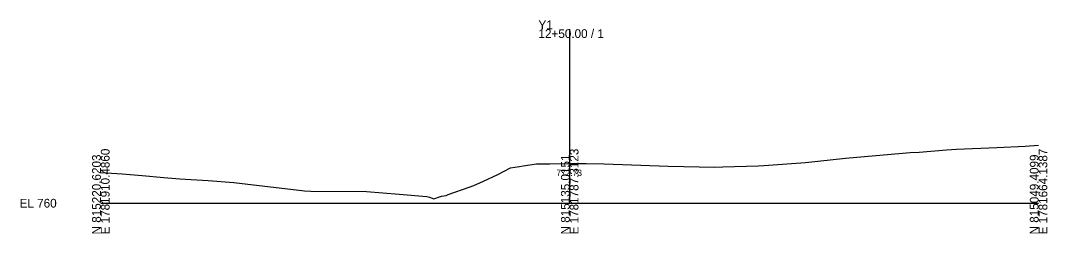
# Model space of a CAD drawing. Extents: x -26 to 3603, y -10 to 9847.
# Drawn here: x -25.7 to 302.8, y 2490.3 to 2558.5 of the extents above; entities that cross this region are included whole.
import ezdxf

# ---------------------------------------------------------------- set-up
doc = ezdxf.new("R2010")
doc.units = 0
for name, color, linetype in [('Exist Cross Section Cell', 7, 'Continuous'), ('Exist XS Center Line Elevation Label', 7, 'Continuous'), ('Exist XS Ground Line', 7, 'Continuous')]:
    doc.layers.add(name, color=color, linetype=linetype)

msp = doc.modelspace()

# ---------------------------------------------------------------- linework, layer by layer
at = {"layer": 'Exist Cross Section Cell'}
for p, q in [((150, 2500), (150, 2555.73)), ((0, 2500), (150, 2500)), ((150, 2500), (300, 2500))]:
    msp.add_line(p, q, dxfattribs=at)
at = {"layer": 'Exist XS Ground Line'}
for p, q in [((261.75, 2516.38), (270.56, 2517.06)), ((270.56, 2517.06), (273.7, 2517.35)), ((273.7, 2517.35), (286.6, 2517.87)), ((286.6, 2517.87), (295.75, 2518.32)), ((295.75, 2518.32), (300, 2518.58)), ((225.42, 2513.06), (238.2, 2514.43)), ((238.2, 2514.43), (258.92, 2516.26)), ((258.92, 2516.26), (261.75, 2516.38)), ((127.02, 2509.19), (131.05, 2511.33)), ((131.05, 2511.33), (132.42, 2511.56)), ((132.42, 2511.56), (133.89, 2511.78)), ((133.89, 2511.78), (135.09, 2511.95)), ((135.09, 2511.95), (139.33, 2512.57)), ((139.33, 2512.57), (143.61, 2512.65)), ((143.61, 2512.65), (150.07, 2512.73)), ((150.07, 2512.73), (155.22, 2512.7)), ((155.22, 2512.7), (161.06, 2512.66)), ((161.06, 2512.66), (181.52, 2511.85)), ((181.52, 2511.85), (196.42, 2511.54)), ((196.42, 2511.54), (198.96, 2511.68)), ((198.96, 2511.68), (210.31, 2512)), ((210.31, 2512), (212.05, 2512.08)), ((212.05, 2512.08), (225.42, 2513.06)), ((0, 2509.87), (6.77, 2509.39)), ((6.77, 2509.39), (13.24, 2508.83)), ((13.24, 2508.83), (20.12, 2508.27)), ((20.12, 2508.27), (25.27, 2507.79)), ((25.27, 2507.79), (34.37, 2507.23)), ((34.37, 2507.23), (42.5, 2506.66)), ((119.31, 2505.72), (122.4, 2507.03)), ((122.4, 2507.03), (127.02, 2509.19)), ((42.5, 2506.66), (65.2, 2504.01)), ((65.2, 2504.01), (67.19, 2503.82)), ((67.19, 2503.82), (85.02, 2503.73)), ((85.02, 2503.73), (95.48, 2502.93)), ((111.09, 2502.8), (117.84, 2505.13)), ((117.84, 2505.13), (119.31, 2505.72)), ((95.48, 2502.93), (104.24, 2502.14)), ((104.24, 2502.14), (105.1, 2501.89)), ((105.1, 2501.89), (106.56, 2501.41)), ((106.56, 2501.41), (108.35, 2502)), ((108.35, 2502), (109, 2502.21)), ((109, 2502.21), (110.5, 2502.49)), ((110.5, 2502.49), (111.09, 2502.8))]:
    msp.add_line(p, q, dxfattribs=at)

# ---------------------------------------------------------------- texts
at = {"layer": 'Exist Cross Section Cell'}
for s, p in [('Y1', (140, 2555.73)), ('12+50.00 / 1', (140, 2552.93)), ('EL 760', (-26, 2498.6))]:
    msp.add_text(s, height=2.8, dxfattribs=at).set_placement(p)
for s, p in [('E 1781910.4860', (2.8, 2490)), ('E 1781787.3123', (152.8, 2490)), ('E 1781664.1387', (302.8, 2490)), ('N 815220.6203', (0, 2490)), ('N 815135.0151', (150, 2490)), ('N 815049.4099', (300, 2490))]:
    msp.add_text(s, height=2.8, rotation=90, dxfattribs=at).set_placement(p)
at = {"layer": 'Exist XS Center Line Elevation Label'}
msp.add_text('772.73', height=2, dxfattribs=at).set_placement((145.75, 2508.73))

doc.saveas('drawing.dxf')
